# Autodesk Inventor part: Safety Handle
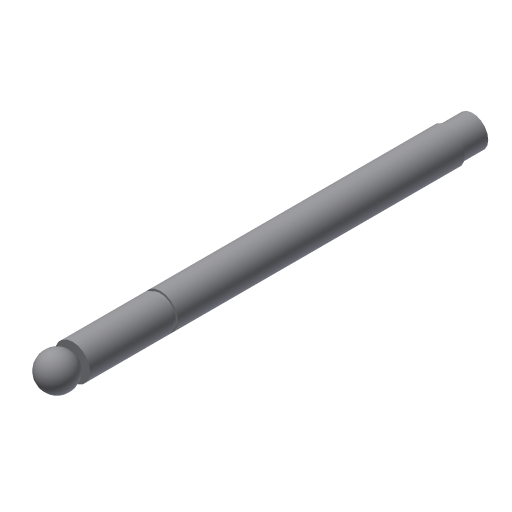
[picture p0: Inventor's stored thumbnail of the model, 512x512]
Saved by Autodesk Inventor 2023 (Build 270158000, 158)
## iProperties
Shininess: 77.0
Length Units: 11269
Angle Units: 11279
Time Units: 11290
Mass Units: 11283
Length Display Precision: 3
Angle Display Precision: 2
Created: 2002-02
Part Number: Safety Handle
Document SubType Name: Modeling
Designer: ***
Density: 1 g/cm^3
Material: Generic
Mass: 54.3914 g
Surface Area: 130.219 cm^2
Volume: 54.3914 cm^3
Appearance: Default
Density: 0.0
Volumn: 0.0
Area: 0.0
PropertySet Name: Model Information
Control State: 0
Master: False
Checked Out: False
Author: ***
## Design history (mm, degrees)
sketch "Sketch1"
  geometry: L1 (0, 205)-(8, 205); L2 (8, 205)-(8, 192); L3 (8, 192)-(9, 192); L4 (9, 192)-(9, 45); L5 (9, 45)-(8, 45); L6 (8, 45)-(8, 43); L7 (8, 43)-(9, 43); L8 (9, 43)-(9, 0); L9 (9, 0)-(0, 0); L10 (0, 0)-(0, 205)
  constraints: 20 end point, 7 parallel, 1 collinear, 1 horizontal, 1 perpendicular
  dimensions: "d0" = 13 distance of L1.end L2.end; "d1" = 2 distance of L4.end L7.end; "d2" = 43 distance of L7.end L8.end; "d3" = 205 distance of L9.end L1.start; "d4" = 16 diameter of L2 L10; "d5" = 18 diameter of L4 L10; "d6" = 16 diameter of L6.end L10
revolve "Revolution1" sketch "Sketch1" stored, may be unused: angle "d7" = 90 deg
sketch "Sketch2"
  geometry: L1 (0, 1)-(0, -17); L2 (-9, 0)-(9, 0) reference; A1 r 9 centre (0, -8) between (0, -17) and (0, 1)
  constraints: 2 end point, 2 point on circle, 1 centre point, 1 midpoint, 1 vertical
  dimensions: "d8" = 9 radius of A1; "d9" = 1 distance from line of L2 L1.start
revolve "Revolution2" sketch "Sketch2" stored, may be unused: angle "d10" = 90 deg
body "Solid1"
